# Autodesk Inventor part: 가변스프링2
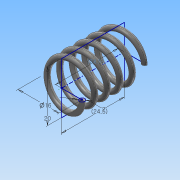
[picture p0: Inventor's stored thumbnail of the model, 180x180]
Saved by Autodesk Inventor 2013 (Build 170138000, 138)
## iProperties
Created: 2018-10
Part Number: 가변스프링2
Material: 스테인리스강
Document SubType Name: Modeling
Designer: Administrator
Density: 8.08 g/cm^3
Mass: 6.27108 g
Surface Area: 15.7574 cm^2
Volume: 0.776124 cm^3
Author: Administrator
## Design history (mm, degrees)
sketch "스케치1"
  geometry: L1 (0, 0)-(0, 24.5); L2 (0, 0)-(8, 0); L3 (0, 24.5)-(8, 24.5); C1 r 1 at (8, 0)
  constraints: 6 end point, 1 centre point, 1 coincident, 1 parallel, 1 perpendicular, 1 vertical
  dimensions: "d0" = 24.5 distance of L1.start L1.end (derived); "d1" = 2 diameter of C1; "d2" = 16 diameter of L2.end L1
feature "코일1" sketch "스케치1" pitch "d3" = 10; turns "d5" = 5; dims "d4" = 24.5 (= d0), "d6" = 0, angle "d7" = 90 deg, angle "d8" = 90 deg, "d9" = 0, "d10" = 0
sketch "스케치2"
  geometry: L1 (24.5, 10)-(0, 10); L2 (0, 10)-(0, -10); L3 (0, -10)-(24.5, -10); L4 (24.5, -10)-(24.5, 10); 2 further points
  constraints: 8 end point, 2 parallel, 1 coincident, 1 horizontal, 1 midpoint, 1 perpendicular
  dimensions: "d11" = 20 distance of L1.end L2.end; "d13" = 24.5 distance of L2.end L3.end (derived)
extrude "돌출1" sketch "스케치2" stored distance "d14" = 24.5 (= d0); taper "d15" = 0 deg
node "솔리드1"
